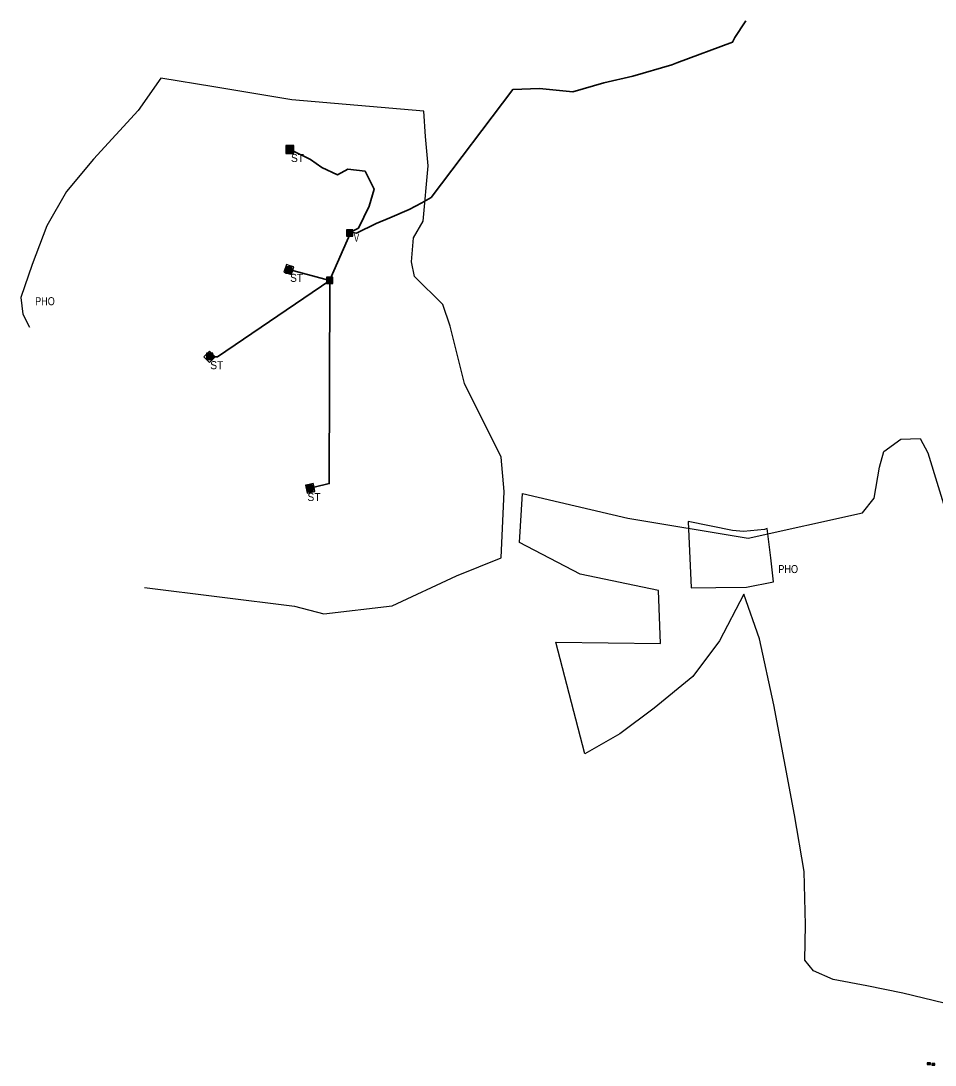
# Model space of a CAD drawing. Extents: x -589836 to -586543, y -1119607 to -1116793.
# Drawn here: x -589836 to -588693, y -1119424 to -1118119 of the extents above; entities that cross this region are included whole.
import ezdxf

# ---------------------------------------------------------------- set-up
doc = ezdxf.new("R2010")
doc.units = 0
doc.header["$LTSCALE"] = 4
for name, color, linetype, lineweight in [('17', 7, 'Continuous', 25), ('18', 7, 'Continuous', 25), ('26', 7, 'Continuous', 25), ('29', 7, 'Continuous', 25), ('45', 7, 'Continuous', 25), ('49', 7, 'Continuous', 25)]:
    doc.layers.add(name, color=color, linetype=linetype, lineweight=lineweight)

msp = doc.modelspace()

# ---------------------------------------------------------------- hatches: boundary and pattern name
at = {"layer": '29'}
for points in [[(-588702.105, -1119421.108), (-588700.203, -1119421.108), (-588700.203, -1119423.123), (-588702.105, -1119423.123)], [(-588696.287, -1119421.78), (-588694.385, -1119421.78), (-588694.385, -1119423.795), (-588696.287, -1119423.795)]]:
    msp.add_hatch(color=256, dxfattribs=at).paths.add_polyline_path(points)
at = {"layer": '49'}
for points in [[(-589503.759, -1118283.658), (-589495.759, -1118283.658), (-589495.759, -1118275.658), (-589503.759, -1118275.658)], [(-589429.243, -1118387.978), (-589421.243, -1118387.978), (-589421.243, -1118379.978), (-589429.243, -1118379.978)], [(-589505.367, -1118434.372), (-589497.367, -1118434.372), (-589497.367, -1118426.372), (-589505.367, -1118426.372)], [(-589454.15, -1118447.17), (-589446.15, -1118447.17), (-589446.15, -1118439.17), (-589454.15, -1118439.17)], [(-589604.261, -1118542.136), (-589596.261, -1118542.136), (-589596.261, -1118534.136), (-589604.261, -1118534.136)], [(-589478.694, -1118707.188), (-589470.694, -1118707.188), (-589470.694, -1118699.188), (-589478.694, -1118699.188)]]:
    msp.add_hatch(color=256, dxfattribs=at).paths.add_polyline_path(points)

# ---------------------------------------------------------------- linework, layer by layer
at = {"layer": '17'}
msp.add_lwpolyline([(-589681.69, -1118826.847), (-589494.095, -1118850.094), (-589457.743, -1118859.906), (-589372.154, -1118849.964), (-589291.675, -1118812.211), (-589235.855, -1118790.07), (-589232.052, -1118706.948), (-589235.996, -1118664.093), (-589281.555, -1118571.935), (-589290.686, -1118536.881), (-589299.818, -1118500.527), (-589308.94, -1118473.264), (-589344.045, -1118438.238), (-589347.961, -1118420.06), (-589345.398, -1118390.187), (-589333.4, -1118369.23), (-589327.139, -1118300.021), (-589330.448, -1118263.305), (-589332.588, -1118231.728), (-589497.541, -1118217.627), (-589594.993, -1118201.498), (-589661.21, -1118190.538), (-589689.737, -1118230.831), (-589745.514, -1118291.933), (-589779.236, -1118332.231), (-589803.863, -1118375.117), (-589821.991, -1118423.19), (-589836.23, -1118464.766), (-589833.609, -1118485.541), (-589825.617, -1118501.482)], dxfattribs=at)
for points in [[(-589494.904, -1118274.801), (-589500.831, -1118274.801), (-589504.904, -1118274.801), (-589504.904, -1118279.658), (-589504.904, -1118284.801), (-589501.367, -1118284.801), (-589498.955, -1118284.801), (-589494.904, -1118284.801), (-589494.904, -1118280.194), (-589494.904, -1118279.658)], [(-589499.467, -1118424.951), (-589504.376, -1118423.344), (-589507.487, -1118432.848), (-589497.983, -1118435.959), (-589494.872, -1118426.455)], [(-589448.428, -1118444.625), (-589451.428, -1118444.625), (-589451.428, -1118441.625), (-589448.428, -1118441.625)], [(-589597.408, -1118534.671), (-589600.36, -1118531.737), (-589607.409, -1118538.83), (-589600.316, -1118545.879), (-589593.267, -1118538.786)], [(-589469.844, -1118701.398), (-589470.733, -1118697.138), (-589475.853, -1118698.206), (-589480.523, -1118699.181), (-589478.48, -1118708.97), (-589470.691, -1118707.344), (-589468.691, -1118706.927)]]:
    msp.add_lwpolyline(points, close=True, dxfattribs=at)
at = {"layer": '18'}
msp.add_lwpolyline([(-588967.596, -1118826.861), (-588929.401, -1118826.454), (-588895.311, -1118819.858), (-588898.812, -1118790.103), (-588903.367, -1118753.227), (-588906.955, -1118754.484), (-588932.966, -1118756.996), (-588946.958, -1118755.74), (-589002.286, -1118744.685), (-588998.251, -1118827.187)], close=True, dxfattribs=at)
at = {"layer": '26'}
for points in [[(-588703.29, -1119423.14), (-588699.29, -1119423.14), (-588699.29, -1119421.14), (-588703.29, -1119421.14)], [(-588697.73, -1119423.79), (-588693.73, -1119423.79), (-588693.73, -1119421.79), (-588697.73, -1119421.79)]]:
    msp.add_lwpolyline(points, close=True, dxfattribs=at)
at = {"layer": '29'}
for points in [[(-588702.105, -1119421.108), (-588700.203, -1119421.108), (-588700.203, -1119423.123), (-588702.105, -1119423.123)], [(-588696.287, -1119421.78), (-588694.385, -1119421.78), (-588694.385, -1119423.795), (-588696.287, -1119423.795)]]:
    msp.add_lwpolyline(points, close=True, dxfattribs=at)
at = {"layer": '45'}
msp.add_lwpolyline([(-588682.003, -1119346.317), (-588734.05, -1119333.837), (-588778.785, -1119324.801), (-588820.939, -1119316.624), (-588845.458, -1119305.866), (-588856.211, -1119292.527), (-588855.351, -1119248.634), (-588857.072, -1119181.934), (-588869.116, -1119110.931), (-588894.924, -1118973.659), (-588912.99, -1118891.037), (-588932.777, -1118835.096), (-588962.887, -1118893.619), (-588996.438, -1118938.373), (-589044.615, -1118977.962), (-589087.629, -1119009.806), (-589131.504, -1119034.764), (-589167.636, -1118895.341), (-589036.872, -1118897.062), (-589039.453, -1118830.793), (-589137.096, -1118810.136), (-589212.801, -1118770.546), (-589209.36, -1118709.441), (-589077.736, -1118740.424), (-588927.185, -1118765.382), (-588784.377, -1118733.539), (-588769.752, -1118715.465), (-588762.87, -1118676.736), (-588757.708, -1118656.941), (-588736.201, -1118641.45), (-588712.113, -1118640.589), (-588702.65, -1118658.663), (-588647.591, -1118837.676)], dxfattribs=at)
at = {"layer": '49', "lineweight": 35}
for points in [[(-589423.803, -1118382.943), (-589416.6, -1118384.27), (-589392.15, -1118372.23), (-589375.08, -1118364.91), (-589350.82, -1118354.77), (-589334.88, -1118346.32), (-589323.33, -1118339.43), (-589221.4, -1118204.77), (-589188.05, -1118203.63), (-589146.37, -1118207.65), (-589107.53, -1118196.43), (-589071.34, -1118187.97), (-589022.64, -1118173.8), (-589016.193, -1118171.48), (-588946.566, -1118145.726), (-588943.705, -1118139.754), (-588930.933, -1118120.28), (-588930.16, -1118118.938)], [(-589499.757, -1118279.825), (-589474.15, -1118292.24), (-589460.16, -1118302.31), (-589440.31, -1118311.15), (-589427.5, -1118304.11), (-589406, -1118306.79), (-589394.76, -1118329.2), (-589400.89, -1118350.5), (-589414.29, -1118378.09), (-589421.52, -1118381.778), (-589423.803, -1118382.943), (-589449.474, -1118441.625), (-589450.15, -1118443.17), (-589501.108, -1118429.715)], [(-589450.15, -1118443.17), (-589590.45, -1118538.7), (-589600.15, -1118538.742)], [(-589474.722, -1118702.893), (-589469.785, -1118701.681), (-589450.88, -1118697.04), (-589450.155, -1118445.019), (-589450.15, -1118443.17)]]:
    msp.add_lwpolyline(points, dxfattribs=at)
at = {"layer": '49'}
for points in [[(-589503.759, -1118283.658), (-589495.759, -1118283.658), (-589495.759, -1118275.658), (-589503.759, -1118275.658)], [(-589429.243, -1118387.978), (-589421.243, -1118387.978), (-589421.243, -1118379.978), (-589429.243, -1118379.978)], [(-589505.367, -1118434.372), (-589497.367, -1118434.372), (-589497.367, -1118426.372), (-589505.367, -1118426.372)], [(-589454.15, -1118447.17), (-589446.15, -1118447.17), (-589446.15, -1118439.17), (-589454.15, -1118439.17)], [(-589604.261, -1118542.136), (-589596.261, -1118542.136), (-589596.261, -1118534.136), (-589604.261, -1118534.136)], [(-589478.694, -1118707.188), (-589470.694, -1118707.188), (-589470.694, -1118699.188), (-589478.694, -1118699.188)]]:
    msp.add_lwpolyline(points, close=True, dxfattribs=at)

# ---------------------------------------------------------------- texts
at = {"layer": '18', "width": 0.85}
for p in [(-589818.435, -1118474.207), (-588889.455, -1118808.94)]:
    msp.add_text('PHO', height=10, dxfattribs=at).set_placement(p)
at = {"layer": '49'}
for s, width, p in [('ST', 0.95, (-589498.585, -1118295.329)), ('V', 0.75, (-589420.12, -1118394.934)), ('ST', 0.95, (-589499.745, -1118445.065)), ('ST', 0.95, (-589599.521, -1118554.176)), ('ST', 0.95, (-589477.975, -1118718.862))]:
    msp.add_text(s, height=10, dxfattribs=dict(at, width=width)).set_placement(p)

doc.saveas('drawing.dxf')
